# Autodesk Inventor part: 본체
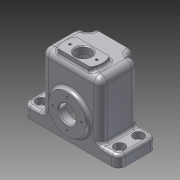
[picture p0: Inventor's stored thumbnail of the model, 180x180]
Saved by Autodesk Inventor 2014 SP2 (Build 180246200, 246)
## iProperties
Created: 2023-12
Part Number: 본체
Material: 알루미늄 6061
Document SubType Name: Modeling
Designer: 거성
Density: 2.71 g/cm^3
Appearance: 알루미늄 - 평지
Mass: 219.911 g
Surface Area: 358.721 cm^2
Volume: 81.1479 cm^3
Author: 거성
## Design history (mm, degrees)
sketch "스케치1"
  geometry: L1 (36, 20)-(-36, 20); L2 (-36, 20)-(-36, -20); L3 (-36, -20)-(36, -20); L4 (36, -20)-(36, 20); L5 (36, 20)-(-36, -20); L6 (-36, 20)-(36, -20); 1 further point
  constraints: 12 end point, 2 midpoint, 2 parallel, 1 horizontal, 1 perpendicular
  dimensions: "d0" = 72 distance of L3.end L2.end; "d1" = 40 distance of L2.end L1.end
extrude "돌출1" new body sketch "스케치1" stored distance "d2" = 62; taper "d3" = 0 deg
fillet "모깎기1" dims "d5" = 7
fillet "모깎기2" dims "d6" = 7
feature "쉘1" dims "d4" = 4
sketch "스케치2"
  geometry: L1 (0, 0)-(48, 0) reference; C1 r 20 at (24, 28); 1 further point
  constraints: 1 centre point, 1 vertical alignment
  dimensions: "d7" = 40 diameter of C1; "d8" = 28 distance from line of C1.centre L1
extrude "돌출2" join sketch "스케치2" distance "d9" = 4; taper "d10" = 0 deg
sketch "스케치3"
  geometry: C1 r 20 at (0, 0) reference; C2 r 9 at (0, 0); 1 further point
  constraints: 1 centre point, 1 coincident
  dimensions: "d11" = 18 diameter of C2
extrude "돌출3" cut sketch "스케치3" distance "d12" = 8; taper "d13" = 0 deg
sketch "스케치4"
  geometry: L1 (48, 0)-(0, 0) reference; C1 r 12 at (24, 28); 1 further point
  constraints: 1 centre point, 1 vertical alignment
  dimensions: "d14" = 24 diameter of C1; "d15" = 28 distance from line of L1 C1.centre
extrude "돌출4" join sketch "스케치4" distance "d16" = 4; taper "d17" = 0 deg
sketch "스케치7" dims "d21" = 30
  geometry: L1 (0, 0)-(0, 15); C1 r 20 at (0, 0) reference; 1 further point
  constraints: 2 end point, 1 coincident, 1 vertical, 1 vertical alignment, 2 other
hole "구멍1" sketch "스케치7" at (0, 15) diameter "d22" = 2.459; stored, may be unused: countersink angle "d26" = 90 deg, drill point angle "d28" = 118 deg; dims "d23" = 8, "d24" = 4, "d25" = 2, "d27" = 8
node "작업 평면2"
sketch "스케치12"
  geometry: L1 (-20, 36)-(20, 36); L2 (20, 36)-(20, 12); L3 (20, 12)-(-20, 12); L4 (-20, 12)-(-20, 36); L5 (-20, 36)-(20, 12); L6 (20, 36)-(-20, 12); L7 (24, 36)-(-24, 36) reference; 4 further points
  constraints: 12 end point, 5 midpoint, 2 parallel, 1 horizontal, 1 perpendicular, 1 vertical alignment
  dimensions: "d42" = 40 distance of L2.end L3.end; "d43" = 24 distance of L1.end L2.end
extrude "돌출7" join sketch "스케치12" stored distance "d44" = 8; taper "d45" = 0 deg
sketch "스케치13"
  geometry: L1 (-20, 36)-(20, 36) reference; 3 further points
  constraints: 1 horizontal alignment
  dimensions: "d46" = 28 distance of point (14, 30) point (-14, 30); "d47" = 14 horizontal distance of point (0, 0) point (-14, 30); "d48" = 6 distance from line of point (-14, 30) L1
hole "구멍2" sketch "스케치13" at (-14, 30), (14, 30) diameter "d49" = 2.459; stored, may be unused: countersink angle "d53" = 90 deg, drill point angle "d55" = 118 deg; dims "d50" = 12, "d51" = 4, "d52" = 2, "d54" = 14
node "작업 평면3"
sketch "스케치14"
  geometry: L1 (-7, -33)-(-7, -7) reference; L2 (0, 0)-(12, 0) reference; L3 (12, 0)-(12, 4) reference; L4 (12, 4)-(23.285, 4) reference; L5 (23.285, 4)-(23.285, -4) reference; L6 (23.285, -4)-(0, -4) reference; L7 (-3, -7)-(-3, -33) reference; L8 (0, -36)-(48, -36) reference; L9 (51, -33)-(51, -7) reference; L10 (48, -4)-(24.715, -4) reference; L11 (24.715, -4)-(24.715, 4) reference; L12 (24.715, 4)-(36, 4) reference; L13 (36, 4)-(36, 0) reference; L14 (36, 0)-(48, 0) reference; L15 (55, -7)-(55, -33) reference; L16 (48, -40)-(0, -40) reference; L17 (74, -40)-(-26, -40); L18 (-26, -40)-(-26, 0); L19 (74, 0)-(74, -40); L20 (74, -40)-(-26, 0); L21 (-26, -40)-(74, 0); L22 (-26, 0)-(12, 0); L23 (36, 0)-(74, 0); L24 (-7, -33)-(-7, -7) reference; L25 (55, -7)-(55, -33) reference; A1 r 7 centre (0, -33) between (-7, -33) and (0, -40) reference; A2 r 7 centre (0, -7) between (0, 0) and (-7, -7) reference; A3 r 3 centre (0, -7) between (0, -4) and (-3, -7) reference; A4 r 3 centre (0, -33) between (-3, -33) and (0, -36) reference; A5 r 3 centre (48, -33) between (48, -36) and (51, -33) reference; A6 r 3 centre (48, -7) between (51, -7) and (48, -4) reference; A7 r 7 centre (48, -7) between (55, -7) and (48, 0) reference; A8 r 7 centre (48, -33) between (48, -40) and (55, -33) reference; A9 r 7 centre (0, -7) between (0, 0) and (-7, -7) reference; A10 r 7 centre (0, -33) between (-7, -33) and (0, -40) reference; A11 r 7 centre (48, -33) between (48, -40) and (55, -33) reference; A12 r 7 centre (48, -7) between (55, -7) and (48, 0) reference; 1 further point
  constraints: 16 end point, 3 parallel, 2 midpoint, 1 horizontal, 1 perpendicular, 1 point on line
  dimensions: "d57" = 100 distance between parallel lines of L19 L18
extrude "돌출8" join sketch "스케치14" distance "d58" = 12; taper "d59" = 0 deg
sketch "스케치15"
  geometry: L1 (48, 36)-(0, 36) reference; L2 (-3, 33)-(-3, 7) reference; L3 (0, 4)-(23.285, 4) reference; L4 (23.285, 4)-(23.285, -4) reference; L5 (23.285, -4)-(12, -4) reference; L6 (12, -4)-(12, 0) reference; L7 (12, 0)-(0, 0) reference; L8 (-7, 7)-(-7, 33) reference; L9 (-26, 40)-(0, 40) reference; L10 (-26, 0)-(-26, 40) reference; L11 (0, 0)-(-26, 0) reference; L12 (51, 7)-(51, 33) reference; L13 (24.715, 4)-(48, 4) reference; L14 (24.715, -4)-(24.715, 4) reference; L15 (36, -4)-(24.715, -4) reference; L16 (36, 0)-(36, -4) reference; L17 (48, 0)-(36, 0) reference; L18 (55, 33)-(55, 7) reference; L19 (48, 40)-(74, 40) reference; L20 (74, 40)-(74, 0) reference; L21 (74, 0)-(48, 0) reference; L22 (0, 40)-(48, 40) reference; A1 r 3 centre (0, 33) between (0, 36) and (-3, 33) reference; A2 r 3 centre (0, 7) between (-3, 7) and (0, 4) reference; A3 r 7 centre (0, 7) between (-7, 7) and (0, 0) reference; A4 r 7 centre (0, 33) between (0, 40) and (-7, 33) reference; A5 r 3 centre (48, 33) between (51, 33) and (48, 36) reference; A6 r 3 centre (48, 7) between (48, 4) and (51, 7) reference; A7 r 7 centre (48, 7) between (48, 0) and (55, 7) reference; A8 r 7 centre (48, 33) between (55, 33) and (48, 40) reference; 5 further points
  constraints: 2 horizontal alignment, 2 vertical alignment
  dimensions: "d60" = 82 distance of point (-17, 30) point (65, 30); "d61" = 41 horizontal distance of point (24, 20) point (-17, 30); "d62" = 10 distance from line of point (-17, 10) L11; "d63" = 20 distance of point (-17, 10) point (-17, 30)
hole "구멍3" sketch "스케치15" at (65, 30), (-17, 30), (-17, 10), (65, 10) diameter "d64" = 6.6; stored, may be unused: countersink angle "d68" = 90 deg, drill point angle "d70" = 118 deg; dims "d65" = 8, "d66" = 11, "d67" = 6.6, "d69" = 12
fillet "모깎기3" dims "d71" = 7
node "작업 평면4"
sketch "스케치16"
  geometry: L1 (-57, 27)-(-29, 27); L2 (-60.321, 17)-(-25.679, 17); L3 (-25.679, 37)-(-60.321, 37); L4 (-63, -4)-(-23, -4) reference; A1 r 20 centre (-43, 27) between (-60.321, 37) and (-60.321, 17); A2 r 20 centre (-43, 27) between (-25.679, 17) and (-25.679, 37); 2 further points
  constraints: 8 end point, 4 point on circle, 2 centre point, 1 coincident, 1 horizontal, 1 midpoint, 1 parallel, 1 vertical alignment
  dimensions: "d75" = 28 distance of L1.start L1.end; "d76" = 31 distance from line of point (-43, 27) L4; "d91" = 20 radius of A1; "d92" = 20 radius of A2; "d94" = 10 distance from line of L3 point (-43, 27); "d95" = 20 distance between parallel lines of L2 L3; "d96" = 10 vertical distance of L2.end point (-43, 27)
extrude "돌출9" join sketch "스케치16" stored distance "d77" = 12; taper "d78" = 0 deg
sketch "스케치17"
  geometry: L1 (25.679, -37)-(60.321, -37) reference; C1 r 8 at (43, -27); 1 further point
  constraints: 1 centre point, 1 vertical alignment
  dimensions: "d79" = 16 diameter of C1; "d97" = 10 distance from line of L1 C1.centre
extrude "돌출10" cut sketch "스케치17" distance "d80" = 20; taper "d81" = 0 deg
sketch "스케치18"
  geometry: 9 further points
  constraints: 2 coincident, 2 other
hole "구멍4" sketch "스케치18" at (57, -27), (29, -27) diameter "d82" = 2.459; stored, may be unused: countersink angle "d86" = 90 deg, drill point angle "d88" = 118 deg; dims "d83" = 8, "d84" = 11, "d85" = 6.6, "d87" = 12
chamfer "모따기1" distance "d98" = 1; stored, may be unused: second distance "d99" = 2, angle "d100" = 45 deg
fillet "모깎기5" dims "d101" = 3
fillet "모깎기6" dims "d102" = 3
fillet "모깎기7" dims "d103" = 3
fillet "모깎기8" dims "d104" = 3
fillet "모깎기9" dims "d105" = 3
fillet "모깎기10" dims "d106" = 3
fillet "모깎기12" dims "d108" = 3
sketch "스케치19"
  geometry: L1 (-24, 4)-(-24, -20) reference; L2 (13, -36)-(-13, -36) reference; 2 further points
  constraints: 1 other
  dimensions: "d111" = 23 distance from line of point (-1, 4) L1; "d112" = 40 distance from line of L2 point (-1, 4)
feature "엠보싱1" sketch "스케치19" dims "d113" = 0.5, "d114" = 0
sketch "스케치21"
  geometry: C1 r 12 at (0, 0) reference; C2 r 8 at (0, 0); 1 further point
  constraints: 1 centre point, 1 coincident
  dimensions: "d122" = 16 diameter of C2
extrude "돌출11" cut sketch "스케치21" distance "d123" = 8; taper "d124" = 0 deg
feature "스레드1" dims "d125" = 10, "d126" = 0
fillet "모깎기15" dims "d127" = 3
fillet "모깎기16" dims "d128" = 5
fillet "모깎기17" dims "d129" = 3
node "솔리드1"
pattern_circular "원형 패턴1" dims angle "d30" = 360 deg
node "절단 모서리 투영1"
node "절단 모서리 투영2"
other parameters: "d41" = -24, "d56" = -12, "d72" = -76
